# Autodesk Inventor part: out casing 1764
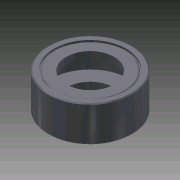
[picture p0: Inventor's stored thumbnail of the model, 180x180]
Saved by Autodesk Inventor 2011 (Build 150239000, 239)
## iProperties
Created: 2009-01
Part Number: out casing 1764
Document SubType Name: Modeling
Designer: pmulligan
Density: 1 g/cm^3
Author: pmulligan
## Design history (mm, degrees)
sketch "Sketch1"
  geometry: L1 (-27.546, 4.227)-(-26.022, 4.227); L2 (-26.022, 4.227)-(-26.022, -5.247); L3 (-26.022, -5.247)-(-27.546, -5.247); L4 (-27.546, -5.247)-(-27.546, 4.227); L5 (-16.434, 9.028)-(-16.434, -15.355)
  constraints: 10 end point, 3 parallel, 1 horizontal, 1 perpendicular
  dimensions: "d0" = 9.4742 distance of L3.end L1.start; "d1" = 1.524 distance of L1.start L1.end; "d2" = 11.1125 distance between parallel lines of L5 L4
revolve "Revolution1" sketch "Sketch1" stored, may be unused: angle "d3" = 90 deg
workplane "Work Plane1"
sketch "Sketch2"
  geometry: C1 r 11.113 at (0, 0); C2 r 6.35 at (0, 0)
  constraints: 2 centre point, 1 coincident
  dimensions: "d5" = 12.7 diameter of C2; "d35" = 22.225 diameter of C1
extrude "Extrusion1" join sketch "Sketch2" distance "d6" = 1.92072; taper "d7" = 0 deg
workplane "Work Plane2"
sketch "Sketch3"
  geometry: C1 r 11.113 at (0, 0); C2 r 6.35 at (0, 0)
  constraints: 2 centre point, 1 coincident
  dimensions: "d9" = 12.7 diameter of C2; "d34" = 22.225 diameter of C1
extrude "Extrusion2" join sketch "Sketch3" distance "d10" = 1.92072; taper "d11" = 0 deg
workplane "Work Plane3"
sketch "Sketch4"
  geometry: C1 r 10.351 at (0, 0)
  constraints: 1 centre point
  dimensions: "d13" = 20.701 diameter of C1
extrude "Extrusion3" cut sketch "Sketch4" distance "d14" = 5.12475; taper "d15" = 0 deg
sketch "Sketch5"
  geometry: C1 r 9.589 at (0, 0) reference; C2 r 9.335 at (0, 0)
  constraints: 1 centre point, 1 coincident
  dimensions: "d16" = 0.254 radial gap between concentric circles of C1 C2
extrude "Extrusion4" cut sketch "Sketch5" distance "d17" = 0.254; taper "d18" = 0 deg
chamfer "Chamfer1" distance "d19" = 0.254; stored, may be unused: second distance "d20" = 3.175, angle "d21" = 45 deg
sketch "Sketch6"
  geometry: C1 r 9.589 at (0, 0) reference; C2 r 9.335 at (0, 0)
  constraints: 1 centre point, 1 coincident
  dimensions: "d22" = 0.254 radial gap between concentric circles of C1 C2
extrude "Extrusion5" cut sketch "Sketch6" distance "d23" = 0.254; taper "d24" = 0 deg
chamfer "Chamfer2" distance "d25" = 0.254; stored, may be unused: second distance "d26" = 3.175, angle "d27" = 45 deg
chamfer "Chamfer3" distance "d28" = 0.254; stored, may be unused: second distance "d29" = 3.175, angle "d30" = 45 deg
chamfer "Chamfer4" distance "d31" = 0.254; stored, may be unused: second distance "d32" = 3.175, angle "d33" = 45 deg
body "Solid1"
other parameters: "d4" = -0.254, "d8" = -0.254, "d12" = 0
